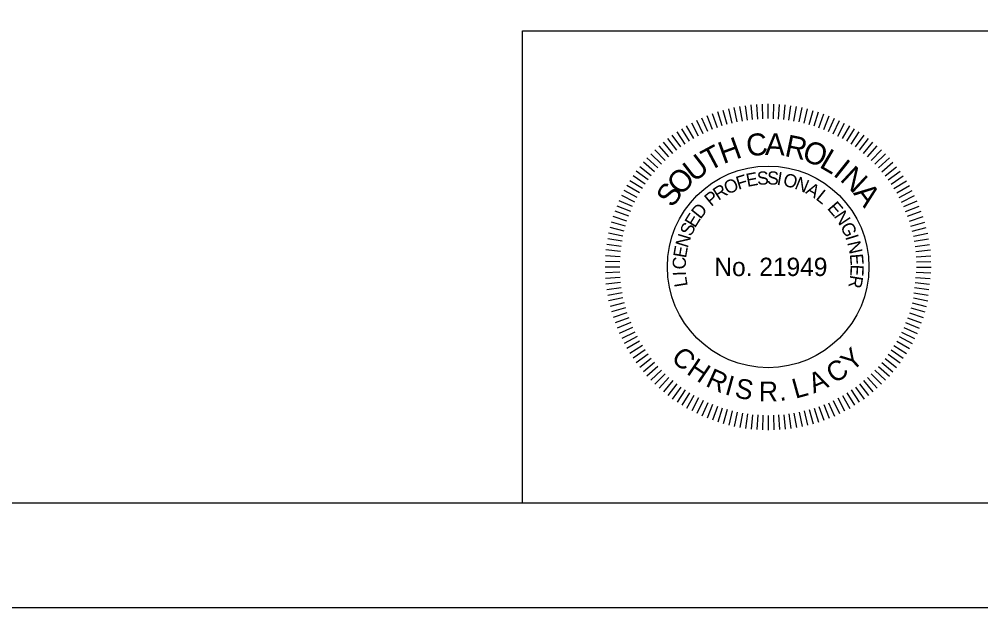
# Model space of a CAD drawing. Extents: x -10371 to -10009, y 1939 to 2167.
# Drawn here: x -10137.7 to -10091.86, y 1939.49 to 1967.55 of the extents above; entities that cross this region are included whole.
import ezdxf

# ---------------------------------------------------------------- set-up
doc = ezdxf.new("R2010")
doc.units = 0
for name, color, linetype in [('BR_BORDER LINES', 7, 'Continuous'), ('BR_DETAILS', 7, 'Continuous'), ('RD_SHT_IplotShp', 7, 'Continuous')]:
    doc.layers.add(name, color=color, linetype=linetype)

msp = doc.modelspace()

# ---------------------------------------------------------------- linework, layer by layer
at = {"layer": 'BR_BORDER LINES'}
for p, q in [((-10113.704, 1966.994), (-10090.579, 1966.994)), ((-10113.704, 1944.493), (-10113.704, 1966.994)), ((-10352.245, 1944.494), (-10015.579, 1944.494))]:
    msp.add_line(p, q, dxfattribs=at)
at = {"layer": 'BR_DETAILS'}
for p, q in [((-10104.182, 1962.465), (-10104.398, 1963.13)), ((-10104.182, 1962.465), (-10104.398, 1963.13)), ((-10103.944, 1962.529), (-10104.136, 1963.2)), ((-10103.944, 1962.529), (-10104.136, 1963.2)), ((-10103.705, 1962.593), (-10103.874, 1963.27)), ((-10103.705, 1962.593), (-10103.874, 1963.27)), ((-10103.467, 1962.657), (-10103.612, 1963.34)), ((-10103.467, 1962.657), (-10103.612, 1963.34)), ((-10103.223, 1962.695), (-10103.344, 1963.383)), ((-10103.223, 1962.695), (-10103.344, 1963.383)), ((-10102.979, 1962.734), (-10103.076, 1963.425)), ((-10102.979, 1962.734), (-10103.076, 1963.425)), ((-10102.735, 1962.773), (-10102.808, 1963.468)), ((-10102.735, 1962.773), (-10102.808, 1963.468)), ((-10102.489, 1962.786), (-10102.537, 1963.482)), ((-10102.489, 1962.786), (-10102.537, 1963.482)), ((-10102.242, 1962.798), (-10102.267, 1963.496)), ((-10102.242, 1962.798), (-10102.267, 1963.496)), ((-10101.995, 1962.811), (-10101.995, 1963.51)), ((-10101.995, 1962.811), (-10101.995, 1963.51)), ((-10101.749, 1962.798), (-10101.724, 1963.496)), ((-10101.749, 1962.798), (-10101.724, 1963.496)), ((-10101.502, 1962.786), (-10101.454, 1963.482)), ((-10101.502, 1962.786), (-10101.454, 1963.482)), ((-10101.256, 1962.773), (-10101.183, 1963.468)), ((-10101.256, 1962.773), (-10101.183, 1963.468)), ((-10101.012, 1962.734), (-10100.915, 1963.425)), ((-10101.012, 1962.734), (-10100.915, 1963.425)), ((-10100.768, 1962.695), (-10100.647, 1963.383)), ((-10100.768, 1962.695), (-10100.647, 1963.383)), ((-10100.524, 1962.657), (-10100.379, 1963.34)), ((-10100.524, 1962.657), (-10100.379, 1963.34)), ((-10100.524, 1962.657), (-10100.379, 1963.34)), ((-10100.285, 1962.593), (-10100.117, 1963.27)), ((-10100.285, 1962.593), (-10100.117, 1963.27)), ((-10100.285, 1962.593), (-10100.117, 1963.27)), ((-10100.047, 1962.529), (-10099.855, 1963.2)), ((-10100.047, 1962.529), (-10099.855, 1963.2)), ((-10100.047, 1962.529), (-10099.855, 1963.2)), ((-10099.809, 1962.465), (-10099.593, 1963.13)), ((-10099.809, 1962.465), (-10099.593, 1963.13)), ((-10099.809, 1962.465), (-10099.593, 1963.13)), ((-10105.094, 1962.087), (-10105.4, 1962.715)), ((-10105.094, 1962.087), (-10105.4, 1962.715)), ((-10104.874, 1962.2), (-10105.158, 1962.838)), ((-10104.874, 1962.2), (-10105.158, 1962.838)), ((-10104.643, 1962.288), (-10104.905, 1962.935)), ((-10104.643, 1962.288), (-10104.905, 1962.935)), ((-10104.413, 1962.376), (-10104.652, 1963.032)), ((-10104.413, 1962.376), (-10104.652, 1963.032)), ((-10099.578, 1962.376), (-10099.339, 1963.032)), ((-10099.578, 1962.376), (-10099.339, 1963.032)), ((-10099.578, 1962.376), (-10099.339, 1963.032)), ((-10099.348, 1962.288), (-10099.086, 1962.935)), ((-10099.348, 1962.288), (-10099.086, 1962.935)), ((-10099.348, 1962.288), (-10099.086, 1962.935)), ((-10099.117, 1962.2), (-10098.833, 1962.838)), ((-10099.117, 1962.2), (-10098.833, 1962.838)), ((-10099.117, 1962.2), (-10098.833, 1962.838)), ((-10098.897, 1962.087), (-10098.591, 1962.715)), ((-10098.897, 1962.087), (-10098.591, 1962.715)), ((-10098.897, 1962.087), (-10098.591, 1962.715)), ((-10105.948, 1961.594), (-10106.338, 1962.173)), ((-10105.948, 1961.594), (-10106.338, 1962.173)), ((-10105.741, 1961.729), (-10106.111, 1962.321)), ((-10105.741, 1961.729), (-10106.111, 1962.321)), ((-10105.534, 1961.863), (-10105.883, 1962.469)), ((-10105.534, 1961.863), (-10105.883, 1962.469)), ((-10105.314, 1961.975), (-10105.642, 1962.592)), ((-10105.314, 1961.975), (-10105.642, 1962.592)), ((-10098.677, 1961.975), (-10098.349, 1962.592)), ((-10098.677, 1961.975), (-10098.349, 1962.592)), ((-10098.677, 1961.975), (-10098.349, 1962.592)), ((-10098.457, 1961.863), (-10098.107, 1962.469)), ((-10098.457, 1961.863), (-10098.107, 1962.469)), ((-10098.457, 1961.863), (-10098.107, 1962.469)), ((-10098.25, 1961.729), (-10097.88, 1962.321)), ((-10098.25, 1961.729), (-10097.88, 1962.321)), ((-10098.25, 1961.729), (-10097.88, 1962.321)), ((-10098.043, 1961.594), (-10097.652, 1962.173)), ((-10098.043, 1961.594), (-10097.652, 1962.173)), ((-10098.043, 1961.594), (-10097.652, 1962.173)), ((-10106.347, 1961.304), (-10106.777, 1961.854)), ((-10106.347, 1961.304), (-10106.777, 1961.854)), ((-10106.155, 1961.46), (-10106.566, 1962.025)), ((-10106.155, 1961.46), (-10106.566, 1962.025)), ((-10097.836, 1961.46), (-10097.425, 1962.025)), ((-10097.836, 1961.46), (-10097.425, 1962.025)), ((-10097.836, 1961.46), (-10097.425, 1962.025)), ((-10097.644, 1961.304), (-10097.214, 1961.854)), ((-10097.644, 1961.304), (-10097.214, 1961.854)), ((-10097.644, 1961.304), (-10097.214, 1961.854)), ((-10106.906, 1960.819), (-10107.391, 1961.321)), ((-10106.906, 1960.819), (-10107.391, 1961.321)), ((-10106.731, 1960.994), (-10107.199, 1961.513)), ((-10106.731, 1960.994), (-10107.199, 1961.513)), ((-10106.539, 1961.149), (-10106.988, 1961.684)), ((-10106.539, 1961.149), (-10106.988, 1961.684)), ((-10097.452, 1961.149), (-10097.003, 1961.684)), ((-10097.452, 1961.149), (-10097.003, 1961.684)), ((-10097.452, 1961.149), (-10097.003, 1961.684)), ((-10097.26, 1960.994), (-10096.792, 1961.513)), ((-10097.26, 1960.994), (-10096.792, 1961.513)), ((-10097.26, 1960.994), (-10096.792, 1961.513)), ((-10097.085, 1960.819), (-10096.6, 1961.321)), ((-10097.085, 1960.819), (-10096.6, 1961.321)), ((-10097.085, 1960.819), (-10096.6, 1961.321)), ((-10107.255, 1960.47), (-10107.774, 1960.937)), ((-10107.255, 1960.47), (-10107.774, 1960.937)), ((-10107.08, 1960.644), (-10107.582, 1961.129)), ((-10107.08, 1960.644), (-10107.582, 1961.129)), ((-10096.911, 1960.644), (-10096.409, 1961.129)), ((-10096.911, 1960.644), (-10096.409, 1961.129)), ((-10096.911, 1960.644), (-10096.409, 1961.129)), ((-10096.736, 1960.47), (-10096.217, 1960.937)), ((-10096.736, 1960.47), (-10096.217, 1960.937)), ((-10096.736, 1960.47), (-10096.217, 1960.937)), ((-10107.565, 1960.086), (-10108.116, 1960.516)), ((-10107.565, 1960.086), (-10108.116, 1960.516)), ((-10107.41, 1960.278), (-10107.945, 1960.727)), ((-10107.41, 1960.278), (-10107.945, 1960.727)), ((-10096.581, 1960.278), (-10096.046, 1960.727)), ((-10096.581, 1960.278), (-10096.046, 1960.727)), ((-10096.581, 1960.278), (-10096.046, 1960.727)), ((-10096.425, 1960.086), (-10095.875, 1960.516)), ((-10096.425, 1960.086), (-10095.875, 1960.516)), ((-10096.425, 1960.086), (-10095.875, 1960.516)), ((-10107.855, 1959.687), (-10108.434, 1960.077)), ((-10107.855, 1959.687), (-10108.434, 1960.077)), ((-10107.721, 1959.894), (-10108.286, 1960.305)), ((-10107.721, 1959.894), (-10108.286, 1960.305)), ((-10096.27, 1959.894), (-10095.705, 1960.305)), ((-10096.27, 1959.894), (-10095.705, 1960.305)), ((-10096.27, 1959.894), (-10095.705, 1960.305)), ((-10096.135, 1959.687), (-10095.557, 1960.077)), ((-10096.135, 1959.687), (-10095.557, 1960.077)), ((-10096.135, 1959.687), (-10095.557, 1960.077)), ((-10108.124, 1959.273), (-10108.73, 1959.622)), ((-10108.124, 1959.273), (-10108.73, 1959.622)), ((-10107.99, 1959.48), (-10108.582, 1959.85)), ((-10107.99, 1959.48), (-10108.582, 1959.85)), ((-10096.001, 1959.48), (-10095.409, 1959.85)), ((-10096.001, 1959.48), (-10095.409, 1959.85)), ((-10096.001, 1959.48), (-10095.409, 1959.85)), ((-10095.867, 1959.273), (-10095.261, 1959.622)), ((-10095.867, 1959.273), (-10095.261, 1959.622)), ((-10095.867, 1959.273), (-10095.261, 1959.622)), ((-10108.349, 1958.833), (-10108.976, 1959.139)), ((-10108.349, 1958.833), (-10108.976, 1959.139)), ((-10108.236, 1959.053), (-10108.853, 1959.38)), ((-10108.236, 1959.053), (-10108.853, 1959.38)), ((-10095.754, 1959.053), (-10095.138, 1959.38)), ((-10095.754, 1959.053), (-10095.138, 1959.38)), ((-10095.754, 1959.053), (-10095.138, 1959.38)), ((-10095.642, 1958.833), (-10095.015, 1959.139)), ((-10095.642, 1958.833), (-10095.015, 1959.139)), ((-10095.642, 1958.833), (-10095.015, 1959.139)), ((-10108.549, 1958.382), (-10109.196, 1958.644)), ((-10108.549, 1958.382), (-10109.196, 1958.644)), ((-10108.461, 1958.613), (-10109.099, 1958.897)), ((-10108.461, 1958.613), (-10109.099, 1958.897)), ((-10095.53, 1958.613), (-10094.892, 1958.897)), ((-10095.53, 1958.613), (-10094.892, 1958.897)), ((-10095.53, 1958.613), (-10094.892, 1958.897)), ((-10095.442, 1958.382), (-10094.794, 1958.644)), ((-10095.442, 1958.382), (-10094.794, 1958.644)), ((-10095.442, 1958.382), (-10094.794, 1958.644)), ((-10108.726, 1957.921), (-10109.391, 1958.137)), ((-10108.726, 1957.921), (-10109.391, 1958.137)), ((-10108.638, 1958.152), (-10109.294, 1958.391)), ((-10108.638, 1958.152), (-10109.294, 1958.391)), ((-10095.353, 1958.152), (-10094.697, 1958.391)), ((-10095.353, 1958.152), (-10094.697, 1958.391)), ((-10095.353, 1958.152), (-10094.697, 1958.391)), ((-10095.265, 1957.921), (-10094.6, 1958.137)), ((-10095.265, 1957.921), (-10094.6, 1958.137)), ((-10095.265, 1957.921), (-10094.6, 1958.137)), ((-10108.854, 1957.444), (-10109.531, 1957.613)), ((-10108.854, 1957.444), (-10109.531, 1957.613)), ((-10108.79, 1957.683), (-10109.461, 1957.875)), ((-10108.79, 1957.683), (-10109.461, 1957.875)), ((-10095.201, 1957.683), (-10094.53, 1957.875)), ((-10095.201, 1957.683), (-10094.53, 1957.875)), ((-10095.201, 1957.683), (-10094.53, 1957.875)), ((-10095.137, 1957.444), (-10094.46, 1957.613)), ((-10095.137, 1957.444), (-10094.46, 1957.613)), ((-10095.137, 1957.444), (-10094.46, 1957.613)), ((-10108.918, 1957.206), (-10109.602, 1957.351)), ((-10108.918, 1957.206), (-10109.602, 1957.351)), ((-10095.073, 1957.206), (-10094.389, 1957.351)), ((-10095.073, 1957.206), (-10094.389, 1957.351)), ((-10095.073, 1957.206), (-10094.389, 1957.351)), ((-10108.995, 1956.718), (-10109.686, 1956.815)), ((-10108.995, 1956.718), (-10109.686, 1956.815)), ((-10108.956, 1956.962), (-10109.644, 1957.083)), ((-10108.956, 1956.962), (-10109.644, 1957.083)), ((-10095.034, 1956.962), (-10094.347, 1957.083)), ((-10095.034, 1956.962), (-10094.347, 1957.083)), ((-10095.034, 1956.962), (-10094.347, 1957.083)), ((-10094.996, 1956.718), (-10094.305, 1956.815)), ((-10094.996, 1956.718), (-10094.305, 1956.815)), ((-10094.996, 1956.718), (-10094.305, 1956.815)), ((-10109.047, 1956.227), (-10109.743, 1956.276)), ((-10109.047, 1956.227), (-10109.743, 1956.276)), ((-10109.034, 1956.474), (-10109.729, 1956.547)), ((-10109.034, 1956.474), (-10109.729, 1956.547)), ((-10094.957, 1956.474), (-10094.262, 1956.547)), ((-10094.957, 1956.474), (-10094.262, 1956.547)), ((-10094.957, 1956.474), (-10094.262, 1956.547)), ((-10094.944, 1956.227), (-10094.248, 1956.276)), ((-10094.944, 1956.227), (-10094.248, 1956.276)), ((-10094.944, 1956.227), (-10094.248, 1956.276)), ((-10109.06, 1955.981), (-10109.757, 1956.005)), ((-10109.06, 1955.981), (-10109.757, 1956.005)), ((-10094.931, 1955.981), (-10094.234, 1956.005)), ((-10094.931, 1955.981), (-10094.234, 1956.005)), ((-10094.931, 1955.981), (-10094.234, 1956.005)), ((-10109.072, 1955.734), (-10109.771, 1955.734)), ((-10109.072, 1955.734), (-10109.771, 1955.734)), ((-10109.06, 1955.488), (-10109.757, 1955.463)), ((-10109.06, 1955.488), (-10109.757, 1955.463)), ((-10094.944, 1955.488), (-10094.248, 1955.464)), ((-10094.944, 1955.488), (-10094.248, 1955.464)), ((-10094.918, 1955.734), (-10094.219, 1955.734)), ((-10094.918, 1955.734), (-10094.219, 1955.734)), ((-10094.918, 1955.734), (-10094.219, 1955.734)), ((-10109.047, 1955.241), (-10109.743, 1955.193)), ((-10109.047, 1955.241), (-10109.743, 1955.193)), ((-10109.034, 1954.995), (-10109.729, 1954.922)), ((-10109.034, 1954.995), (-10109.729, 1954.922)), ((-10094.996, 1954.999), (-10094.304, 1954.926)), ((-10094.996, 1954.999), (-10094.304, 1954.926)), ((-10094.97, 1955.243), (-10094.276, 1955.195)), ((-10094.97, 1955.243), (-10094.276, 1955.195)), ((-10108.995, 1954.751), (-10109.686, 1954.653)), ((-10108.995, 1954.751), (-10109.686, 1954.653)), ((-10108.956, 1954.507), (-10109.644, 1954.386)), ((-10108.956, 1954.507), (-10109.644, 1954.386)), ((-10095.047, 1954.509), (-10094.361, 1954.388)), ((-10095.047, 1954.509), (-10094.361, 1954.388)), ((-10095.021, 1954.754), (-10094.333, 1954.657)), ((-10095.021, 1954.754), (-10094.333, 1954.657)), ((-10108.918, 1954.263), (-10109.602, 1954.118)), ((-10108.918, 1954.263), (-10109.602, 1954.118)), ((-10108.854, 1954.024), (-10109.531, 1953.855)), ((-10108.854, 1954.024), (-10109.531, 1953.855)), ((-10095.137, 1954.024), (-10094.46, 1953.855)), ((-10095.137, 1954.024), (-10094.46, 1953.855)), ((-10095.073, 1954.263), (-10094.389, 1954.118)), ((-10095.073, 1954.263), (-10094.389, 1954.118)), ((-10108.79, 1953.786), (-10109.461, 1953.594)), ((-10108.79, 1953.786), (-10109.461, 1953.594)), ((-10108.726, 1953.547), (-10109.391, 1953.331)), ((-10095.265, 1953.547), (-10094.6, 1953.331)), ((-10095.265, 1953.547), (-10094.6, 1953.331)), ((-10095.201, 1953.786), (-10094.53, 1953.594)), ((-10095.201, 1953.786), (-10094.53, 1953.594)), ((-10108.638, 1953.317), (-10109.294, 1953.078)), ((-10108.638, 1953.317), (-10109.294, 1953.078)), ((-10108.549, 1953.086), (-10109.196, 1952.825)), ((-10108.549, 1953.086), (-10109.196, 1952.825)), ((-10095.442, 1953.086), (-10094.794, 1952.825)), ((-10095.442, 1953.086), (-10094.794, 1952.825)), ((-10095.353, 1953.317), (-10094.697, 1953.078)), ((-10095.353, 1953.317), (-10094.697, 1953.078)), ((-10108.461, 1952.856), (-10109.099, 1952.572)), ((-10108.461, 1952.856), (-10109.099, 1952.572)), ((-10108.349, 1952.636), (-10108.976, 1952.33)), ((-10108.349, 1952.636), (-10108.976, 1952.33)), ((-10095.642, 1952.636), (-10095.015, 1952.33)), ((-10095.642, 1952.636), (-10095.015, 1952.33)), ((-10095.53, 1952.856), (-10094.892, 1952.572)), ((-10095.53, 1952.856), (-10094.892, 1952.572)), ((-10108.236, 1952.416), (-10108.853, 1952.088)), ((-10108.236, 1952.416), (-10108.853, 1952.088)), ((-10108.124, 1952.196), (-10108.73, 1951.846)), ((-10108.124, 1952.196), (-10108.73, 1951.846)), ((-10095.867, 1952.196), (-10095.261, 1951.846)), ((-10095.867, 1952.196), (-10095.261, 1951.846)), ((-10095.754, 1952.416), (-10095.138, 1952.088)), ((-10095.754, 1952.416), (-10095.138, 1952.088)), ((-10107.99, 1951.989), (-10108.582, 1951.619)), ((-10107.99, 1951.989), (-10108.582, 1951.619)), ((-10107.855, 1951.782), (-10108.434, 1951.391)), ((-10107.855, 1951.782), (-10108.434, 1951.391)), ((-10096.135, 1951.782), (-10095.557, 1951.391)), ((-10096.135, 1951.782), (-10095.557, 1951.391)), ((-10096.001, 1951.989), (-10095.409, 1951.619)), ((-10096.001, 1951.989), (-10095.409, 1951.619)), ((-10107.721, 1951.575), (-10108.286, 1951.164)), ((-10107.721, 1951.575), (-10108.286, 1951.164)), ((-10107.565, 1951.383), (-10108.116, 1950.953)), ((-10107.565, 1951.383), (-10108.116, 1950.953)), ((-10107.41, 1951.191), (-10107.945, 1950.742)), ((-10107.41, 1951.191), (-10107.945, 1950.742)), ((-10096.581, 1951.191), (-10096.046, 1950.742)), ((-10096.581, 1951.191), (-10096.046, 1950.742)), ((-10096.425, 1951.383), (-10095.875, 1950.953)), ((-10096.425, 1951.383), (-10095.875, 1950.953)), ((-10096.27, 1951.575), (-10095.705, 1951.164)), ((-10096.27, 1951.575), (-10095.705, 1951.164)), ((-10107.255, 1950.999), (-10107.774, 1950.531)), ((-10107.255, 1950.999), (-10107.774, 1950.531)), ((-10107.08, 1950.824), (-10107.582, 1950.339)), ((-10107.08, 1950.824), (-10107.582, 1950.339)), ((-10096.911, 1950.824), (-10096.409, 1950.339)), ((-10096.911, 1950.824), (-10096.409, 1950.339)), ((-10096.736, 1950.999), (-10096.217, 1950.531)), ((-10096.736, 1950.999), (-10096.217, 1950.531)), ((-10106.906, 1950.65), (-10107.391, 1950.148)), ((-10106.906, 1950.65), (-10107.391, 1950.148)), ((-10106.731, 1950.475), (-10107.199, 1949.956)), ((-10106.731, 1950.475), (-10107.199, 1949.956)), ((-10106.539, 1950.32), (-10106.988, 1949.785)), ((-10106.539, 1950.32), (-10106.988, 1949.785)), ((-10097.452, 1950.32), (-10097.003, 1949.785)), ((-10097.452, 1950.32), (-10097.003, 1949.785)), ((-10097.26, 1950.475), (-10096.792, 1949.956)), ((-10097.085, 1950.65), (-10096.6, 1950.148)), ((-10097.085, 1950.65), (-10096.6, 1950.148)), ((-10106.347, 1950.164), (-10106.777, 1949.614)), ((-10106.347, 1950.164), (-10106.777, 1949.614)), ((-10106.155, 1950.009), (-10106.566, 1949.443)), ((-10106.155, 1950.009), (-10106.566, 1949.443)), ((-10105.948, 1949.874), (-10106.338, 1949.296)), ((-10105.948, 1949.874), (-10106.338, 1949.296)), ((-10098.043, 1949.874), (-10097.652, 1949.296)), ((-10098.043, 1949.874), (-10097.652, 1949.296)), ((-10097.836, 1950.009), (-10097.425, 1949.443)), ((-10097.836, 1950.009), (-10097.425, 1949.443)), ((-10097.644, 1950.164), (-10097.214, 1949.614)), ((-10097.644, 1950.164), (-10097.214, 1949.614)), ((-10105.741, 1949.74), (-10106.111, 1949.148)), ((-10105.741, 1949.74), (-10106.111, 1949.148)), ((-10105.534, 1949.605), (-10105.883, 1949)), ((-10105.534, 1949.605), (-10105.883, 1949)), ((-10105.314, 1949.493), (-10105.642, 1948.877)), ((-10105.314, 1949.493), (-10105.642, 1948.877)), ((-10105.094, 1949.381), (-10105.4, 1948.754)), ((-10105.094, 1949.381), (-10105.4, 1948.754)), ((-10098.897, 1949.381), (-10098.591, 1948.754)), ((-10098.897, 1949.381), (-10098.591, 1948.754)), ((-10098.677, 1949.493), (-10098.349, 1948.877)), ((-10098.677, 1949.493), (-10098.349, 1948.877)), ((-10098.457, 1949.605), (-10098.107, 1949)), ((-10098.457, 1949.605), (-10098.107, 1949)), ((-10098.25, 1949.74), (-10097.88, 1949.148)), ((-10098.25, 1949.74), (-10097.88, 1949.148)), ((-10104.874, 1949.269), (-10105.158, 1948.631)), ((-10104.874, 1949.269), (-10105.158, 1948.631)), ((-10104.643, 1949.181), (-10104.905, 1948.533)), ((-10104.643, 1949.181), (-10104.905, 1948.533)), ((-10104.413, 1949.092), (-10104.652, 1948.436)), ((-10104.413, 1949.092), (-10104.652, 1948.436)), ((-10104.182, 1949.004), (-10104.398, 1948.339)), ((-10104.182, 1949.004), (-10104.398, 1948.339)), ((-10103.944, 1948.94), (-10104.136, 1948.269)), ((-10103.944, 1948.94), (-10104.136, 1948.269)), ((-10103.705, 1948.876), (-10103.874, 1948.198)), ((-10103.705, 1948.876), (-10103.874, 1948.198)), ((-10100.285, 1948.876), (-10100.117, 1948.198)), ((-10100.285, 1948.876), (-10100.117, 1948.198)), ((-10100.047, 1948.94), (-10099.855, 1948.269)), ((-10100.047, 1948.94), (-10099.855, 1948.269)), ((-10099.809, 1949.004), (-10099.593, 1948.339)), ((-10099.809, 1949.004), (-10099.593, 1948.339)), ((-10099.578, 1949.092), (-10099.339, 1948.436)), ((-10099.578, 1949.092), (-10099.339, 1948.436)), ((-10099.348, 1949.181), (-10099.086, 1948.533)), ((-10099.348, 1949.181), (-10099.086, 1948.533)), ((-10099.117, 1949.269), (-10098.833, 1948.631)), ((-10099.117, 1949.269), (-10098.833, 1948.631)), ((-10103.467, 1948.812), (-10103.612, 1948.128)), ((-10103.467, 1948.812), (-10103.612, 1948.128)), ((-10103.223, 1948.773), (-10103.344, 1948.086)), ((-10103.223, 1948.773), (-10103.344, 1948.086)), ((-10102.979, 1948.735), (-10103.076, 1948.043)), ((-10102.979, 1948.735), (-10103.076, 1948.043)), ((-10102.735, 1948.696), (-10102.808, 1948.001)), ((-10102.735, 1948.696), (-10102.808, 1948.001)), ((-10102.489, 1948.683), (-10102.537, 1947.987)), ((-10102.489, 1948.683), (-10102.537, 1947.987)), ((-10102.242, 1948.67), (-10102.267, 1947.973)), ((-10102.242, 1948.67), (-10102.267, 1947.973)), ((-10101.995, 1948.657), (-10101.995, 1947.958)), ((-10101.995, 1948.657), (-10101.995, 1947.958)), ((-10101.749, 1948.67), (-10101.724, 1947.973)), ((-10101.749, 1948.67), (-10101.724, 1947.973)), ((-10101.502, 1948.683), (-10101.454, 1947.987)), ((-10101.502, 1948.683), (-10101.454, 1947.987)), ((-10101.256, 1948.696), (-10101.183, 1948.001)), ((-10101.256, 1948.696), (-10101.183, 1948.001)), ((-10101.012, 1948.735), (-10100.915, 1948.043)), ((-10101.012, 1948.735), (-10100.915, 1948.043)), ((-10100.768, 1948.773), (-10100.647, 1948.086)), ((-10100.768, 1948.773), (-10100.647, 1948.086)), ((-10100.524, 1948.812), (-10100.379, 1948.128)), ((-10100.524, 1948.812), (-10100.379, 1948.128))]:
    msp.add_line(p, q, dxfattribs=at)
msp.add_circle((-10101.995, 1955.743), 4.805, dxfattribs=at)
at = {"layer": 'RD_SHT_IplotShp'}
msp.add_lwpolyline([(-10370.578, 2159.494), (-10010.578, 2159.494), (-10010.578, 1939.494), (-10370.578, 1939.494)], close=True, dxfattribs=at)

# ---------------------------------------------------------------- texts
at = {"layer": 'BR_DETAILS'}
for s, height, rotation, p in [('H', 1.048, 19.9102, (-10104.136, 1960.636)), ('C', 1.048, 6.8832, (-10102.978, 1960.993)), ('A', 1.048, 357.9448, (-10102.151, 1961.082)), ('R', 1.048, 348.267, (-10101.251, 1961.032)), ('O', 1.048, 339.3286, (-10100.438, 1960.852)), ('T', 1.048, 28.0947, (-10104.811, 1960.282)), ('L', 1.048, 329.6507, (-10099.602, 1960.518)), ('U', 1.048, 37.7726, (-10105.534, 1959.744)), ('I', 1.048, 321.4663, (-10098.946, 1960.128)), ('O', 1.048, 47.4504, (-10106.156, 1959.092)), ('N', 1.048, 317.0007, (-10098.614, 1959.877)), ('O', 0.628, 25.285, (-10103.927, 1959.172)), ('F', 0.628, 17.0454, (-10103.416, 1959.414)), ('E', 0.628, 10.5018, (-10102.989, 1959.552)), ('S', 0.628, 3.4002, (-10102.51, 1959.645)), ('S', 0.628, 356.8566, (-10102.062, 1959.679)), ('I', 0.628, 350.313, (-10101.613, 1959.66)), ('O', 0.628, 346.0455, (-10101.323, 1959.621)), ('N', 0.628, 337.8059, (-10100.774, 1959.485)), ('S', 1.048, 54.9027, (-10106.555, 1958.524)), ('R', 0.628, 32.9611, (-10104.368, 1958.884)), ('A', 0.628, 329.5663, (-10100.25, 1959.271)), ('L', 0.628, 321.3267, (-10099.763, 1958.984)), ('A', 1.048, 307.3229, (-10097.967, 1959.25)), ('P', 0.628, 39.5047, (-10104.711, 1958.593)), ('D', 0.628, 51.1611, (-10105.23, 1957.985)), ('E', 0.628, 310.8083, (-10099.208, 1958.522)), ('E', 0.628, 58.2627, (-10105.483, 1957.568)), ('N', 0.628, 303.7068, (-10098.886, 1958.157)), ('S', 0.628, 64.8063, (-10105.668, 1957.159)), ('G', 0.628, 295.4672, (-10098.572, 1957.686)), ('N', 0.628, 73.0458, (-10105.833, 1956.618)), ('I', 0.628, 287.2276, (-10098.329, 1957.175)), ('E', 0.628, 80.1474, (-10105.912, 1956.137)), ('N', 0.628, 282.96, (-10098.233, 1956.899)), ('E', 0.628, 274.7205, (-10098.106, 1956.347)), ('C', 0.628, 87.8235, (-10105.929, 1955.61)), ('E', 0.628, 267.6189, (-10098.061, 1955.862)), ('I', 0.628, 92.0911, (-10105.908, 1955.318)), ('R', 0.628, 260.5173, (-10098.077, 1955.375)), ('L', 0.628, 99.1926, (-10105.826, 1954.837)), ('C', 0.942, 317.0914, (-10106.669, 1951.34)), ('Y', 0.942, 42.1707, (-10098.009, 1950.709)), ('H', 0.942, 326.011, (-10105.93, 1950.668)), ('C', 0.942, 33.2512, (-10098.838, 1950.151)), ('R', 0.942, 335.6684, (-10105.023, 1950.08)), ('A', 0.942, 23.5938, (-10099.821, 1949.701)), ('I', 0.942, 344.5879, (-10104.108, 1949.679)), ('S', 0.942, 349.0441, (-10103.631, 1949.533)), ('R', 0.942, 359.8228, (-10102.441, 1949.337)), ('L', 0.942, 15.4265, (-10100.701, 1949.453)), ('.', 0.942, 8.7423, (-10101.442, 1949.345))]:
    msp.add_text(s, height=height, rotation=rotation, dxfattribs=at).set_placement(p)
msp.add_text('No. 21949', height=0.8737, dxfattribs=at).set_placement((-10104.562, 1955.306))

doc.saveas('drawing.dxf')
